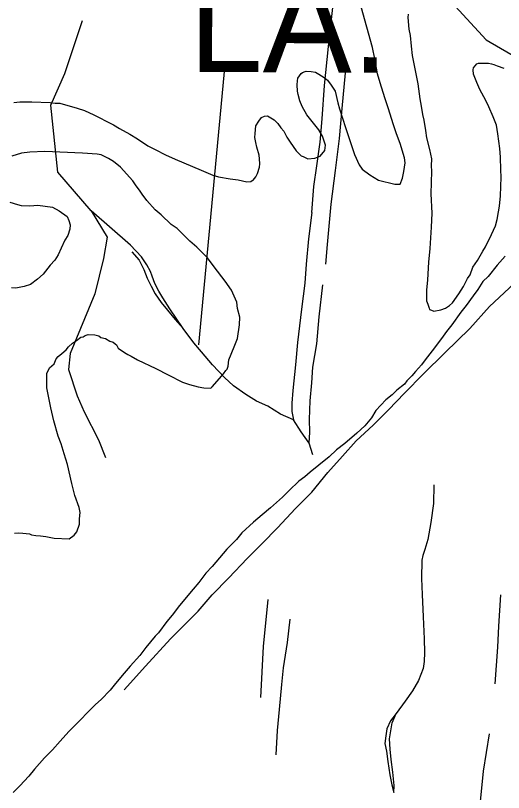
# Model space of a CAD drawing. Extents: x 3161514 to 3199414, y 831166 to 856601.
# Drawn here: x 3185603 to 3186581, y 845160 to 846719 of the extents above; entities that cross this region are included whole.
import ezdxf

# ---------------------------------------------------------------- set-up
doc = ezdxf.new("R2010")
doc.units = 0
for name, color, linetype in [('V-SITE-VEGE', 7, 'Continuous'), ('V-TOPO-GNAM-IDEN', 7, 'Continuous'), ('V-TOPO-SHOR', 7, 'Continuous')]:
    doc.layers.add(name, color=color, linetype=linetype)

msp = doc.modelspace()

# ---------------------------------------------------------------- linework, layer by layer
at = {"layer": 'V-SITE-VEGE'}
for points in [[(3186318.5, 846654.8), (3186296.3, 846736.3)], [(3186390.1, 846722), (3186389.8, 846715.2), (3186391.8, 846691.8), (3186394.3, 846679), (3186396.3, 846657.6), (3186398.5, 846639), (3186405, 846605.7), (3186409.9, 846582.2), (3186413.6, 846551.9), (3186416, 846537.2), (3186419.2, 846520.6), (3186421.7, 846508.8), (3186424.8, 846488.3), (3186427.1, 846473.6), (3186433, 846450), (3186437.1, 846431.4), (3186436.6, 846417.8), (3186437.2, 846407.1), (3186435.4, 846361.4), (3186437.8, 846322.5), (3186436.7, 846294.3), (3186434, 846251.6), (3186431, 846224.5), (3186428.7, 846188.6), (3186426.9, 846168.3), (3186427, 846146.9), (3186429.7, 846140), (3186432.3, 846132.1), (3186433.2, 846129.1), (3186437, 846128), (3186441.8, 846125.9), (3186455.5, 846128.3), (3186465.3, 846131.8), (3186473.3, 846137.3), (3186479.4, 846142.9), (3186491.8, 846160.9), (3186501.1, 846175.1), (3186509.5, 846191.3), (3186514.6, 846198.9), (3186520.1, 846214.2), (3186529.3, 846227.5), (3186539.8, 846246.5), (3186545, 846255.1), (3186557.6, 846279.9), (3186565.1, 846297.1), (3186568.5, 846309.6), (3186571.1, 846325.1), (3186573.5, 846336.6), (3186575.2, 846357), (3186576.7, 846394.8), (3186576.3, 846409.4), (3186575.3, 846434.8), (3186574.1, 846452.3), (3186570.4, 846481.6), (3186567.1, 846499.2), (3186561, 846516), (3186552, 846535.8), (3186545.7, 846548.7), (3186533.9, 846570.5), (3186527.7, 846584.4), (3186521.5, 846601.2), (3186520.9, 846609.9), (3186521, 846613.8), (3186528.2, 846622.3), (3186531.1, 846623.2), (3186540.9, 846623.8), (3186551.6, 846623.3), (3186557.3, 846622.1), (3186562.2, 846621), (3186568.8, 846617.8), (3186582.3, 846613.4)], [(3185672.5, 846544.8), (3185682.1, 846543.4), (3185691.8, 846543), (3185726.4, 846532.9), (3185740.9, 846528.5), (3185760, 846520), (3185770.5, 846514.7), (3185785.7, 846506.3), (3185799.1, 846500), (3185811.4, 846492.7), (3185832.4, 846481.2), (3185847.5, 846471.8), (3185868.4, 846457.4), (3185882.7, 846450), (3185903.7, 846439.5), (3185922.8, 846431), (3185975.4, 846408.5), (3185998.3, 846398.9), (3186009.9, 846395.5), (3186033.1, 846391.7), (3186049.5, 846389.1), (3186066.8, 846385.5), (3186074.7, 846386.2), (3186077.6, 846388), (3186079.6, 846388.9), (3186084.7, 846395.5), (3186087.9, 846402.2), (3186092.3, 846414.7), (3186092.6, 846421.5), (3186092, 846431.2), (3186091.3, 846439), (3186087, 846454.7), (3186084.5, 846464.5), (3186082.9, 846474.3), (3186083.2, 846482.1), (3186084.8, 846497.6), (3186091, 846507.1), (3186096.2, 846514.7), (3186102.1, 846517.3), (3186108, 846518.1), (3186121.3, 846509.8), (3186125, 846506.7), (3186128.8, 846502.7), (3186135.2, 846493.7), (3186140.8, 846486.7), (3186147.1, 846474.8), (3186153.5, 846464.8), (3186165.5, 846447.8), (3186175.8, 846437.7), (3186179.7, 846436.5), (3186189.2, 846431.3), (3186202.9, 846432.7), (3186213.7, 846437.2), (3186222.9, 846448.5), (3186224.3, 846459.1), (3186218.2, 846476.8), (3186210.9, 846489.8), (3186195.2, 846509.8), (3186186.8, 846519.9), (3186177.7, 846536.8), (3186173.3, 846547.6), (3186169.9, 846560.4), (3186168.2, 846567.3), (3186167.8, 846579.9), (3186168.1, 846587.7), (3186169.3, 846593.5), (3186175.5, 846603), (3186178.4, 846604.8), (3186183.4, 846606.5), (3186185.4, 846607.4), (3186196, 846607), (3186204.7, 846605.7), (3186211.4, 846601.6), (3186221.8, 846594.4), (3186228.4, 846589.2), (3186235.8, 846579.2), (3186244.1, 846567.2), (3186249, 846543.7), (3186252.4, 846531.9), (3186264.6, 846494.5), (3186282.9, 846440.3), (3186291.8, 846419.5), (3186298.3, 846410.5), (3186313.4, 846399.2), (3186330.5, 846388.9), (3186363.2, 846380.8), (3186373.9, 846380.4), (3186379.2, 846392.8), (3186381.7, 846406.3), (3186384.3, 846423.7), (3186382.8, 846433.5), (3186378.5, 846449.2), (3186375.1, 846460), (3186366.2, 846483.7), (3186360.1, 846501.5), (3186350.6, 846532), (3186343.7, 846553.6), (3186334.2, 846584.1), (3186329, 846601.9), (3186323.4, 846632.2), (3186318.5, 846654.8)], [(3185599.5, 846544.7), (3185611.3, 846546.2), (3185621, 846545.8), (3185635.6, 846546.2), (3185672.5, 846544.8)], [(3185914.8, 846300), (3185895.1, 846319.3), (3185882.8, 846329.5), (3185866.1, 846347.6), (3185856.8, 846360.6), (3185851.3, 846368.6), (3185844.9, 846377.6), (3185842.1, 846381.6), (3185838.4, 846387.6), (3185813.2, 846414.8), (3185799.1, 846426.1), (3185789.6, 846432.3), (3185774.3, 846439.7), (3185766.6, 846440.9), (3185737.5, 846443), (3185661.8, 846446), (3185631.6, 846445.2), (3185615, 846443), (3185595.3, 846436.9)], [(3185591.7, 846344.7), (3185607.1, 846340.2), (3185613.9, 846338), (3185631.3, 846337.3), (3185647.9, 846338.6), (3185676.9, 846334.6), (3185690.2, 846327.2), (3185706.3, 846315.9), (3185709.9, 846308), (3185712.5, 846299.1), (3185712.1, 846290.4), (3185707.8, 846277.9), (3185701.6, 846268.5), (3185694.1, 846252.2), (3185688.7, 846238.8), (3185681.5, 846228.4), (3185672.4, 846218.1), (3185658.1, 846200.1), (3185647, 846189.9), (3185633, 846179.7), (3185620.2, 846175.4), (3185603.5, 846172.1), (3185594.8, 846172.5)], [(3185600.9, 845680.2), (3185608.7, 845680.9), (3185617.4, 845680.6), (3185631, 845679.1), (3185634.8, 845677), (3185643.5, 845675.7), (3185653.2, 845675.3), (3185663.8, 845673.9), (3185680.2, 845670.3), (3185710.3, 845669.2), (3185720.3, 845676.6), (3185725.5, 845683.2), (3185730.9, 845698.5), (3185731.3, 845709.2), (3185732.8, 845721.8), (3185730.3, 845731.6), (3185721.5, 845756.2), (3185715.6, 845779.8), (3185707.4, 845818.1), (3185700.4, 845839.7), (3185694.4, 845859.4), (3185688.2, 845875.2), (3185679.7, 845905.7), (3185673.9, 845932.1), (3185665.7, 845972.3), (3185665.5, 845990.8), (3185665.9, 846000.5), (3185671.2, 846012), (3185680.2, 846020.4), (3185684.5, 846029.9), (3185688.6, 846034.6), (3185695.6, 846041.2), (3185704.7, 846048.6), (3185708.8, 846054.3), (3185716.9, 846061.7), (3185724.9, 846067.3), (3185733.9, 846073.7), (3185738.7, 846074.5), (3185742.7, 846077.3), (3185748.6, 846079), (3185762.2, 846078.4), (3185769.9, 846076.2), (3185773.7, 846073.1), (3185783.3, 846070.8), (3185791.9, 846065.6), (3185798.6, 846063.4), (3185802.4, 846060.4), (3185805.2, 846058.3), (3185808.8, 846051.3), (3185821.1, 846043.1), (3185827.8, 846038.9), (3185834.5, 846035.8), (3185847.8, 846028.4), (3185884, 846010.5), (3185908.8, 845997.9), (3185937.4, 845983.1), (3185951.8, 845978.7), (3185969.2, 845974.1), (3185980.7, 845971.7), (3185994.3, 845971.2), (3185997.4, 845974), (3186011.6, 845991), (3186019.8, 846000.4), (3186024.9, 846007), (3186027, 846009.8), (3186029.1, 846015.6), (3186030.6, 846028.1), (3186041.3, 846054), (3186047.8, 846071.2), (3186051.8, 846098.3), (3186052.4, 846113.8), (3186048.2, 846131.5), (3186046.8, 846144.2), (3186036, 846167.9), (3186023.1, 846185.9), (3186000.9, 846215), (3185988, 846233), (3185966.5, 846254.3), (3185952.3, 846266.5), (3185941.1, 846277.6), (3185927.1, 846291.8), (3185914.8, 846300)], [(3186585.1, 846236), (3186568.9, 846218.2), (3186550.5, 846195.6), (3186540.3, 846185.3), (3186530, 846169.1), (3186520.8, 846156.9), (3186506.4, 846137), (3186496.1, 846123.8), (3186477.7, 846098.3), (3186467.4, 846085), (3186460.2, 846075.6), (3186446.9, 846057.6), (3186438.7, 846046.3), (3186424.4, 846028.4), (3186417.2, 846018), (3186405, 846004.8), (3186397.8, 845996.3), (3186387.7, 845986), (3186382.6, 845979.4), (3186367.5, 845967.4), (3186358.4, 845958), (3186345.4, 845947.8), (3186325.1, 845926.3), (3186316.8, 845912), (3186303.5, 845896), (3186287.4, 845881.1), (3186263.2, 845860.6), (3186246.2, 845847.7), (3186232.1, 845833.6), (3186211, 845816.9), (3186193.9, 845803), (3186182.9, 845793.7), (3186170.8, 845784.5), (3186151.6, 845765.8), (3186138.5, 845752.7), (3186114.3, 845731.2), (3186097.2, 845717.3), (3186080.1, 845702.4), (3186056.9, 845681), (3186045.7, 845667.8), (3186026.5, 845648.1), (3185996.9, 845613.3), (3185984.8, 845600.2), (3185970.4, 845581.3), (3185959.2, 845568.1), (3185931.7, 845535.1), (3185917.3, 845516.2), (3185906.1, 845503.1), (3185889.7, 845480.4), (3185882.6, 845473.8), (3185864.2, 845451.2), (3185851.9, 845435.2), (3185832.6, 845413.6), (3185820.4, 845399.5), (3185803.1, 845378.7), (3185792.8, 845365.5), (3185774.6, 845346.8), (3185763.5, 845336.5), (3185746.3, 845319.7), (3185734.1, 845306.6), (3185709.9, 845282.2), (3185692.6, 845263.4), (3185677.3, 845245.6), (3185661.1, 845229.7), (3185640.8, 845207.1), (3185629.6, 845193), (3185611.3, 845173.3), (3185598.2, 845160.2)]]:
    msp.add_lwpolyline(points, dxfattribs=at)
at = {"layer": 'V-TOPO-SHOR'}
for p, q in [((3185970.5, 846058.4), (3186023.6, 846620.6)), ((3186553.2, 846135.2), (3186603.1, 846181.3))]:
    msp.add_line(p, q, dxfattribs=at)
for points in [[(3186897, 846496.9), (3186974.8, 847243), (3186900.5, 847349.1), (3186840.4, 847349.1), (3186691.9, 847175.8), (3186614.1, 847133.4), (3186546.9, 847087.4), (3186324.1, 846900), (3186469.1, 846755), (3186546.9, 846670.1), (3186596.4, 846641.8), (3186709.6, 846595.9), (3186815.7, 846560.5), (3186882.8, 846549.9), (3186904.1, 846553.4)], [(3186197.3, 846323.6), (3186201.3, 846376.1), (3186207.4, 846417.5), (3186214.1, 846465.2), (3186217.5, 846512.1), (3186222.3, 846578.9), (3186230.2, 846656.6), (3186237.5, 846716.8), (3186245.1, 846790.3), (3186252.4, 846825.5), (3186256.6, 846891.9), (3186261.9, 846941.6), (3186270.9, 847008.1)], [(3185833.2, 846258.5), (3185754.8, 846327.1), (3185687.6, 846404.9), (3185673.5, 846539.3), (3185701.8, 846602.9), (3185737.1, 846709)], [(3186236, 846340.4), (3186244.8, 846408.3), (3186252.5, 846472.2), (3186257.6, 846532.5), (3186266.9, 846625.2)], [(3186225, 846219.9), (3186228.8, 846259.8), (3186236, 846340.4)], [(3185754.8, 846327.1), (3185786.7, 846274.1), (3185779.6, 846231.7), (3185761.9, 846160.9), (3185712.4, 846040.7), (3185708.9, 846008.9), (3185726.5, 845955.8), (3185740.7, 845924), (3185769, 845867.4), (3185783.1, 845832.1)], [(3186197.3, 846323.6), (3186190.4, 846271.3), (3186185.4, 846220.1), (3186183.1, 846182.3), (3186176.1, 846129.6), (3186168, 846063.3), (3186164.2, 846018), (3186159.1, 845966.8), (3186157, 845941.3), (3186157.1, 845924.6), (3186160.3, 845908)], [(3185836, 846244.6), (3185850.6, 846228.4), (3185860.5, 846209.4), (3185866.9, 846192.3), (3185874.6, 846176.2), (3185882.8, 846160.7), (3185895, 846143.5), (3185907.3, 846127.9), (3185922.7, 846109.3), (3185939.3, 846091), (3185912.4, 846130.3), (3185898.5, 846152.3), (3185890, 846165.9), (3185881.9, 846181.2), (3185876.8, 846196.1), (3185873.7, 846205.4), (3185866.1, 846218.9), (3185855.8, 846234.6), (3185833.2, 846258.5)], [(3186191.4, 845861.3), (3186193.2, 845883.4), (3186192.7, 845908.8), (3186194, 845945.9), (3186196.9, 845981.8), (3186198.8, 846013.3), (3186206.9, 846060.5), (3186212.1, 846114.8), (3186218.8, 846178.9)], [(3185820.8, 845366), (3185863.3, 845413.4), (3185913.6, 845468.4), (3185932.1, 845486.9), (3185969.1, 845523.9), (3185997.1, 845556.6), (3186030.9, 845590.8), (3186067.4, 845629.4), (3186097.4, 845659.9), (3186128.2, 845691.1), (3186164.2, 845729.9), (3186197, 845762.7), (3186228.9, 845802.2), (3186258.4, 845834.6), (3186286.2, 845866), (3186320, 845897.1), (3186350.9, 845927.7), (3186382.6, 845961.3), (3186421.1, 845999.8), (3186463.9, 846042), (3186513.9, 846091.2), (3186553.2, 846135.2)], [(3186199.2, 845837.3), (3186191.4, 845861.3), (3186175.7, 845883.5), (3186160.3, 845908), (3186134.4, 845918.9), (3186108.8, 845935.4), (3186086.1, 845945.3), (3186064.7, 845958.5), (3186040.1, 845976.1), (3186022.2, 845992.9), (3185998.2, 846018.1), (3185975.8, 846044.5), (3185960.6, 846062.3), (3185939.3, 846091)], [(3186441.7, 845777.3), (3186441.1, 845739.8), (3186436, 845701.7), (3186429.6, 845667.5), (3186423.4, 845647.6), (3186419.8, 845635.7), (3186417.5, 845626), (3186417.1, 845589.7), (3186418.5, 845557.3)], [(3186418.5, 845557.3), (3186420, 845512.5), (3186422.1, 845468.5), (3186422.8, 845440.8), (3186422.5, 845422.8), (3186420.1, 845409.2), (3186411.1, 845384.8), (3186399, 845364.2), (3186384, 845343), (3186366.5, 845318.8)], [(3186564.8, 845377.8), (3186570.1, 845451.5), (3186572.2, 845493.8), (3186576.2, 845556.8)], [(3186109, 845547.1), (3186099.7, 845453.2), (3186093.8, 845350.6)], [(3186153.1, 845507.6), (3186147.5, 845461.3), (3186139.7, 845409.9), (3186136, 845376.6), (3186131.7, 845326.9), (3186127.5, 845284.3), (3186124.7, 845235.8)], [(3186366.5, 845318.8), (3186355, 845304), (3186347.8, 845288), (3186345.3, 845273.8), (3186343.6, 845258.2), (3186346.9, 845242.7), (3186349.3, 845222.2), (3186353.2, 845195.6), (3186357.7, 845175.6), (3186361.5, 845160.1), (3186362.1, 845174.2), (3186359.3, 845200.7), (3186356.3, 845226.6), (3186354.1, 845247.3), (3186352.7, 845268), (3186356, 845287.6), (3186358.4, 845299.8), (3186366.5, 845318.8)], [(3186534.7, 845135.2), (3186541.3, 845202.6), (3186553.3, 845277.5)]]:
    msp.add_lwpolyline(points, dxfattribs=at)

# ---------------------------------------------------------------- texts
at = {"layer": 'V-TOPO-GNAM-IDEN'}
msp.add_text('LA.', height=200, rotation=359.7335, dxfattribs=at).set_placement((3185949.9, 846606.1))

doc.saveas('drawing.dxf')
